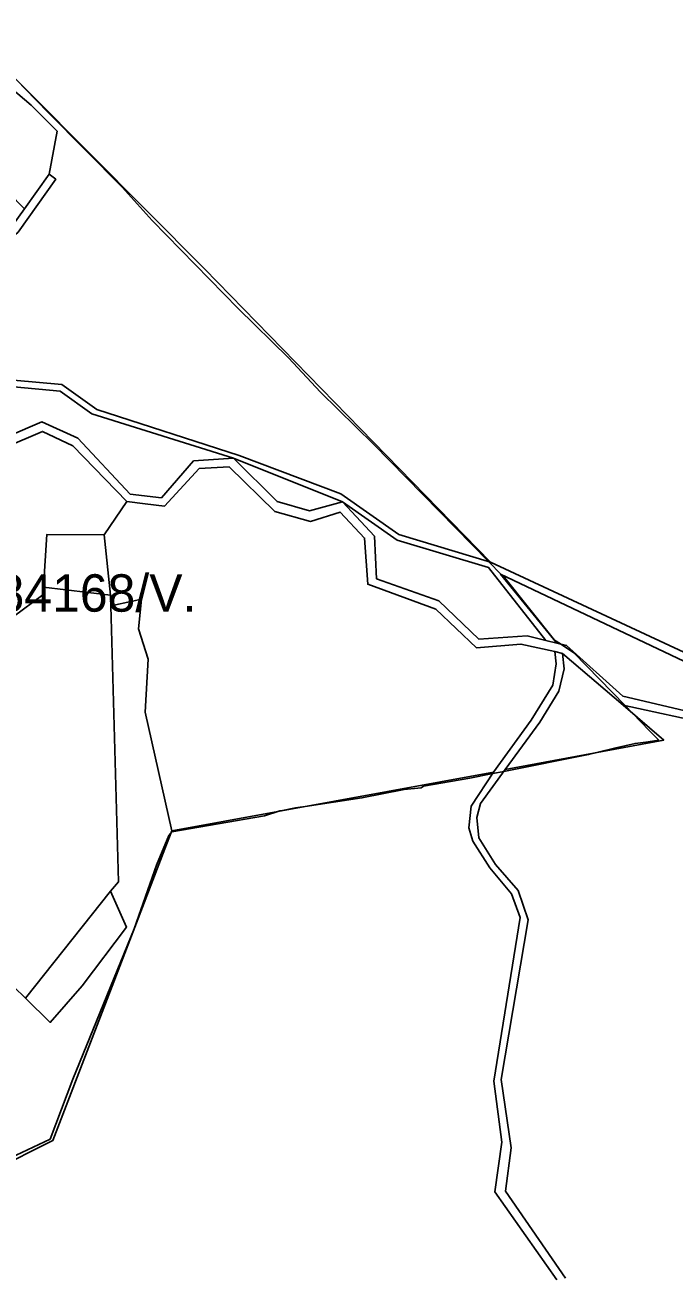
# Model space of a CAD drawing. Extents: x -477304 to -465429, y -1159113 to -1149210.
# Drawn here: x -471512 to -471252, y -1157746 to -1157244 of the extents above; entities that cross this region are included whole.
import ezdxf

# ---------------------------------------------------------------- set-up
doc = ezdxf.new("R2010")
doc.units = 0
for name, color, linetype in [('BPEJ_s', 7, 'Continuous'), ('orna_s', 7, 'Continuous'), ('ostatni_s', 7, 'Continuous'), ('PUPFL_s', 7, 'Continuous'), ('trav_porost_s', 7, 'Continuous'), ('voda_s', 7, 'Continuous')]:
    doc.layers.add(name, color=color, linetype=linetype)

msp = doc.modelspace()

# ---------------------------------------------------------------- linework, layer by layer
at = {"layer": 'BPEJ_s'}
for points in [[(-471595.75, -1157222.6), (-471575.33, -1157220.26), (-471562.35, -1157219.83), (-471553.07, -1157228.99), (-471531.73, -1157250.04), (-471512.53, -1157269.92), (-471503.21, -1157279.57), (-471473.45, -1157309.58), (-471461.33, -1157322.98), (-471426.88, -1157358.29), (-471406.67, -1157378.07), (-471393.7, -1157391.89)], [(-471512.53, -1157269.92), (-471503.21, -1157279.57), (-471473.45, -1157309.58), (-471461.33, -1157322.98), (-471426.88, -1157358.29), (-471406.67, -1157378.07), (-471393.7, -1157391.89), (-471372.43, -1157412.73), (-471326.23, -1157459.87), (-471321.02, -1157465.18), (-471319.9, -1157466.33), (-471299.7, -1157491.42), (-471297.38, -1157492.97), (-471292.04, -1157496.53), (-471271.41, -1157517.74), (-471268.47, -1157520.76), (-471261.63, -1157527.79), (-471257.86, -1157531.67), (-471263.12, -1157532.47), (-471264.11, -1157532.57), (-471267.37, -1157532.9), (-471275.69, -1157534.88), (-471282.24, -1157536.44), (-471286.09, -1157537.36), (-471320.08, -1157544.12), (-471324.59, -1157545.02), (-471333.75, -1157546.84), (-471352.44, -1157550.12), (-471353.29, -1157550.76), (-471360.1, -1157551.4), (-471377.11, -1157554.8), (-471399.85, -1157558.18), (-471402.85, -1157558.63), (-471403.84, -1157558.82), (-471409.65, -1157559.91), (-471409.89, -1157559.98), (-471410.08, -1157560.04), (-471416.25, -1157562.03), (-471453.46, -1157568.41), (-471453.86, -1157568.88), (-471454.74, -1157569.9), (-471459.63, -1157581.81), (-471468.56, -1157607.33), (-471493.23, -1157667.73), (-471502.38, -1157691.77), (-471575.33, -1157726.01)], [(-471393.7, -1157391.89), (-471372.43, -1157412.73), (-471326.23, -1157459.87), (-471321.02, -1157465.18), (-471319.9, -1157466.33), (-471299.7, -1157491.42), (-471297.38, -1157492.97), (-471292.04, -1157496.53), (-471271.41, -1157517.74), (-471268.47, -1157520.76), (-471261.63, -1157527.79), (-471257.86, -1157531.67), (-471263.12, -1157532.47), (-471264.11, -1157532.57), (-471267.37, -1157532.9), (-471275.69, -1157534.88), (-471282.24, -1157536.44), (-471286.09, -1157537.36), (-471320.08, -1157544.12), (-471324.59, -1157545.02), (-471333.75, -1157546.84), (-471352.44, -1157550.12), (-471353.29, -1157550.76), (-471360.1, -1157551.4), (-471377.11, -1157554.8), (-471399.85, -1157558.18), (-471402.85, -1157558.63), (-471403.84, -1157558.82), (-471409.65, -1157559.91), (-471409.89, -1157559.98), (-471410.08, -1157560.04), (-471416.25, -1157562.03), (-471453.46, -1157568.41), (-471453.86, -1157568.88), (-471454.74, -1157569.9), (-471459.63, -1157581.81), (-471468.56, -1157607.33), (-471493.23, -1157667.73), (-471502.38, -1157691.77), (-471575.33, -1157726.01)]]:
    msp.add_lwpolyline(points, dxfattribs=at)
at = {"layer": 'orna_s'}
msp.add_lwpolyline([(-471547.05, -1157601.11), (-471550.71, -1157597.52), (-471578.01, -1157570.79), (-471575.79, -1157569.55), (-471551.61, -1157541.71), (-471517.22, -1157482.14), (-471505.29, -1157473.28), (-471505.08, -1157470.14), (-471478.05, -1157473.4), (-471477.93, -1157477.66), (-471474.94, -1157588.42), (-471478.16, -1157592.2), (-471512.23, -1157635.18), (-471521.57, -1157626.07)], close=True, dxfattribs=at)
at = {"layer": 'ostatni_s'}
msp.add_lwpolyline([(-471543.22, -1157347.03), (-471517.46, -1157325.02), (-471512.71, -1157318.3), (-471502.81, -1157304.3), (-471500.07, -1157306.41), (-471515.26, -1157327.67), (-471549.07, -1157357.35), (-471559.01, -1157359.89), (-471576.42, -1157355.04), (-471583.09, -1157351.54), (-471561.13, -1157347.06), (-471552.66, -1157355.1)], close=True, dxfattribs=at)
for points in [[(-471517.02, -1157387.07), (-471497.65, -1157388.84), (-471483.63, -1157398.8), (-471426.43, -1157417.31), (-471385.65, -1157432.75), (-471362.35, -1157449.02), (-471325.5, -1157460.09), (-471247.87, -1157496.21)], [(-471247.87, -1157499.9), (-471321.41, -1157465), (-471298.87, -1157492.61), (-471303.3, -1157491.55), (-471326.26, -1157462.26), (-471362.95, -1157451.28), (-471384.86, -1157435.97), (-471428.64, -1157418.43), (-471485.58, -1157400.54), (-471498.34, -1157391.43), (-471516.9, -1157389.72)], [(-471298.81, -1157748.32), (-471323.77, -1157712.94), (-471320.89, -1157692.99), (-471324.1, -1157668.5), (-471313.55, -1157602.83), (-471317.07, -1157593.28), (-471325.68, -1157582.87), (-471332.55, -1157572.14), (-471334.11, -1157566.83), (-471333.18, -1157558.12), (-471324.21, -1157544.43), (-471309.15, -1157523.6), (-471300.46, -1157509.56), (-471299.1, -1157500.92), (-471299.68, -1157496.07), (-471296.53, -1157496.75), (-471295.91, -1157503.02), (-471298.03, -1157511.94), (-471305.59, -1157524.41), (-471319.55, -1157543.39), (-471329.52, -1157557.03), (-471330.99, -1157562.69), (-471330.17, -1157570.8), (-471323.51, -1157581.47), (-471314.33, -1157592.01), (-471310.31, -1157603.74), (-471321.13, -1157667.8), (-471317.13, -1157695.26), (-471319.51, -1157712.72), (-471295.33, -1157747.56)]]:
    msp.add_lwpolyline(points, dxfattribs=at)
at = {"layer": 'PUPFL_s'}
for points in [[(-471247.87, -1157496.21), (-471325.5, -1157460.09), (-471440.37, -1157342.39), (-471533.35, -1157249.01), (-471563.69, -1157218.21), (-471654.84, -1157226.07), (-471692.75, -1157229.08), (-471730.12, -1157232.17), (-471744.05, -1157220.16), (-471749.26, -1157215.67), (-471768.33, -1157211.35), (-471783.71, -1157212.42), (-471791.25, -1157210.9), (-471806.11, -1157198.23), (-471831.21, -1157186.83), (-471856.12, -1157184.54), (-471923.49, -1157140.7), (-471958.22, -1157107.83), (-471975.7, -1157085.58), (-471987.92, -1157051.4), (-472009.29, -1157017.07), (-472016.29, -1156972.29)], [(-471516.9, -1157389.72), (-471498.34, -1157391.43), (-471485.58, -1157400.54), (-471428.64, -1157418.43), (-471444.75, -1157419.39), (-471457.66, -1157434.24), (-471470.18, -1157432.79), (-471491.2, -1157410.31), (-471505.7, -1157403.77), (-471532.65, -1157415.33)], [(-471234.12, -1157522.9), (-471272.36, -1157513.92), (-471294.89, -1157493.57), (-471298.87, -1157492.61), (-471321.41, -1157465), (-471247.87, -1157499.9)], [(-471521.57, -1157626.07), (-471512.23, -1157635.18), (-471502.32, -1157644.92), (-471489.46, -1157630.24), (-471471.74, -1157606.72), (-471478.16, -1157592.2), (-471474.94, -1157588.42), (-471477.93, -1157477.66), (-471469.21, -1157475.8), (-471465.62, -1157475.04), (-471466.81, -1157486.96), (-471463.03, -1157499.14), (-471464.12, -1157520.32), (-471453.5, -1157567.94), (-471456.33, -1157575.22), (-471467.61, -1157604.95), (-471501.33, -1157692.34), (-471525.35, -1157704.38)], [(-471295.33, -1157747.56), (-471319.51, -1157712.72), (-471317.13, -1157695.26), (-471321.13, -1157667.8), (-471310.31, -1157603.74), (-471314.33, -1157592.01), (-471323.51, -1157581.47), (-471330.17, -1157570.8), (-471330.99, -1157562.69), (-471329.52, -1157557.03), (-471319.55, -1157543.39), (-471255.9, -1157531.54), (-471272.19, -1157517.57), (-471236.42, -1157525.38)], [(-471525.35, -1157704.38), (-471501.33, -1157692.34), (-471467.61, -1157604.95), (-471456.33, -1157575.22), (-471453.5, -1157567.94), (-471324.21, -1157544.43), (-471333.18, -1157558.12), (-471334.11, -1157566.83), (-471332.55, -1157572.14), (-471325.68, -1157582.87), (-471317.07, -1157593.28), (-471313.55, -1157602.83), (-471324.1, -1157668.5), (-471320.89, -1157692.99), (-471323.77, -1157712.94), (-471298.81, -1157748.32)]]:
    msp.add_lwpolyline(points, dxfattribs=at)
for points in [[(-471549.07, -1157357.35), (-471515.26, -1157327.67), (-471500.07, -1157306.41), (-471502.81, -1157304.3), (-471499.55, -1157287.13), (-471510, -1157276.65), (-471537.72, -1157253.19), (-471533.35, -1157249.01), (-471440.37, -1157342.39), (-471325.5, -1157460.09), (-471362.35, -1157449.02), (-471385.65, -1157432.75), (-471426.43, -1157417.31), (-471483.63, -1157398.8), (-471497.65, -1157388.84), (-471517.02, -1157387.07), (-471529.9, -1157379.78), (-471545.05, -1157364.1), (-471559.67, -1157362.83), (-471577.82, -1157356.58), (-471592.05, -1157346.84), (-471583.09, -1157351.54), (-471576.42, -1157355.04), (-471559.01, -1157359.89)], [(-471499.55, -1157287.13), (-471502.81, -1157304.3), (-471512.71, -1157318.3), (-471557.72, -1157272.34), (-471537.72, -1157253.19), (-471510, -1157276.65)], [(-471384.86, -1157435.97), (-471398.23, -1157439.49), (-471411.13, -1157435.83), (-471428.64, -1157418.43)], [(-471313.27, -1157493.04), (-471299.68, -1157496.07), (-471299.1, -1157500.92), (-471300.46, -1157509.56), (-471309.15, -1157523.6), (-471324.21, -1157544.43), (-471453.5, -1157567.94), (-471464.12, -1157520.32), (-471463.03, -1157499.14), (-471466.81, -1157486.96), (-471465.62, -1157475.04), (-471469.21, -1157475.8), (-471477.93, -1157477.66), (-471478.05, -1157473.4), (-471480.71, -1157449.15), (-471471.61, -1157435.79), (-471464.21, -1157436.67), (-471456.4, -1157437.59), (-471442.5, -1157422.54), (-471430.45, -1157421.91), (-471412.08, -1157439.79), (-471397.78, -1157443.78), (-471385.91, -1157440.06), (-471376.07, -1157450.47), (-471374.76, -1157469.02), (-471347.42, -1157478.96), (-471331.16, -1157494.52)], [(-471346.19, -1157475.68), (-471371.21, -1157466.8), (-471372.12, -1157449.75), (-471384.86, -1157435.97), (-471362.95, -1157451.28), (-471326.26, -1157462.26), (-471303.3, -1157491.55), (-471310.68, -1157489.77), (-471330.17, -1157491.04)], [(-471296.53, -1157496.75), (-471272.19, -1157517.57), (-471255.9, -1157531.54), (-471319.55, -1157543.39), (-471305.59, -1157524.41), (-471298.03, -1157511.94), (-471295.91, -1157503.02)]]:
    msp.add_lwpolyline(points, close=True, dxfattribs=at)
at = {"layer": 'trav_porost_s'}
msp.add_lwpolyline([(-471534.14, -1157419.89), (-471505.37, -1157407.66), (-471493.3, -1157413.36), (-471471.61, -1157435.79), (-471480.71, -1157449.15), (-471503.7, -1157449.03), (-471505.08, -1157470.14), (-471505.29, -1157473.28), (-471517.22, -1157482.14)], dxfattribs=at)
for points in [[(-471505.08, -1157470.14), (-471503.7, -1157449.03), (-471480.71, -1157449.15), (-471478.05, -1157473.4)], [(-471478.16, -1157592.2), (-471471.74, -1157606.72), (-471489.46, -1157630.24), (-471502.32, -1157644.92), (-471512.23, -1157635.18)]]:
    msp.add_lwpolyline(points, close=True, dxfattribs=at)
at = {"layer": 'voda_s'}
for points in [[(-471532.65, -1157415.33), (-471505.7, -1157403.77), (-471491.2, -1157410.31), (-471470.18, -1157432.79), (-471457.66, -1157434.24), (-471444.75, -1157419.39), (-471428.64, -1157418.43), (-471411.13, -1157435.83), (-471398.23, -1157439.49), (-471384.86, -1157435.97), (-471372.12, -1157449.75), (-471371.21, -1157466.8), (-471346.19, -1157475.68), (-471330.17, -1157491.04), (-471310.68, -1157489.77), (-471303.3, -1157491.55), (-471298.87, -1157492.61), (-471294.89, -1157493.57), (-471272.36, -1157513.92), (-471234.12, -1157522.9)], [(-471236.42, -1157525.38), (-471272.19, -1157517.57), (-471296.53, -1157496.75), (-471299.68, -1157496.07), (-471313.27, -1157493.04), (-471331.16, -1157494.52), (-471347.42, -1157478.96), (-471374.76, -1157469.02), (-471376.07, -1157450.47), (-471385.91, -1157440.06), (-471397.78, -1157443.78), (-471412.08, -1157439.79), (-471430.45, -1157421.91), (-471442.5, -1157422.54), (-471456.4, -1157437.59), (-471464.21, -1157436.67), (-471471.61, -1157435.79), (-471493.3, -1157413.36), (-471505.37, -1157407.66), (-471534.14, -1157419.89)]]:
    msp.add_lwpolyline(points, dxfattribs=at)

# ---------------------------------------------------------------- texts
at = {"layer": 'BPEJ_s'}
msp.add_text('84168/V.', height=15, dxfattribs=at).set_placement((-471523.89, -1157480.01))

doc.saveas('drawing.dxf')
